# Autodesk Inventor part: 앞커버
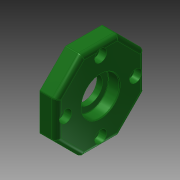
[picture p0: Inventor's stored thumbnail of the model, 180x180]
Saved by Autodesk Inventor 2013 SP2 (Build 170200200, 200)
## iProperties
Created: 2015-11
Part Number: 앞커버
Material: 알루미늄 6061
Document SubType Name: Modeling
Designer: mduedu
Density: 1 g/cm^3
Author: mduedu
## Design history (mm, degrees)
sketch "스케치5" dims "d66" = 58
  geometry: L1 (12.012, 29)-(29, 12.012); L2 (29, 12.012)-(29, -12.012); L3 (29, -12.012)-(12.012, -29); L4 (12.012, -29)-(-12.012, -29); L5 (-12.012, -29)-(-29, -12.012); L6 (-29, -12.012)-(-29, 12.012); L7 (-29, 12.012)-(-12.012, 29); L8 (-12.012, 29)-(12.012, 29); 4 further points
  constraints: 16 end point, 2 coincident, 2 vertical alignment, 1 midpoint, 19 other
extrude "돌출2" new body sketch "스케치5" distance "d67" = 11; taper "d68" = 0 deg
sketch "스케치6"
  geometry: C1 r 16 at (0, 0); 1 further point
  constraints: 1 centre point, 1 coincident
  dimensions: "d69" = 32 diameter of C1
extrude "돌출3" join sketch "스케치6" distance "d70" = 3; taper "d71" = 0 deg
hole "구멍7" diameter "d98" = 28; stored, may be unused: countersink angle "d102" = 90 deg, drill point angle "d104" = 0 deg; dims "d99" = 6, "d100" = 4, "d101" = 2, "d103" = 3, "d145" = 10, "d146" = 10
hole "구멍8" diameter "d107" = 25; stored, may be unused: countersink angle "d111" = 90 deg, drill point angle "d113" = 0 deg; dims "d108" = 6, "d109" = 4, "d110" = 2, "d112" = 7.3, "d143" = 10, "d144" = 10
hole "구멍9" diameter "d116" = 17; stored, may be unused: countersink angle "d120" = 90 deg, drill point angle "d122" = 0 deg; dims "d114" = 10, "d115" = 10, "d117" = 6, "d118" = 4, "d119" = 2, "d121" = 7.7
chamfer "모따기2" distance "d123" = 0.6; stored, may be unused: second distance "d124" = 2, angle "d125" = 30 deg
fillet "모깎기11" dims "d126" = 0.3
fillet "모깎기12" dims "d127" = 1
fillet "모깎기13" dims "d128" = 3
fillet "모깎기14" dims "d129" = 3
fillet "모깎기15" dims "d130" = 0.3
sketch "스케치8" dims "d131" = 46
  geometry: 3 further points
  constraints: 2 vertical alignment, 1 coincident, 2 other
hole "구멍10" sketch "스케치8" at (0, 23) diameter "d132" = 4.5; stored, may be unused: countersink angle "d136" = 90 deg, drill point angle "d138" = 0 deg; dims "d133" = 6, "d134" = 8, "d135" = 4.6, "d137" = 7.7
node "솔리드2"
pattern_circular "원형 패턴4" dims angle "d140" = 360 deg
